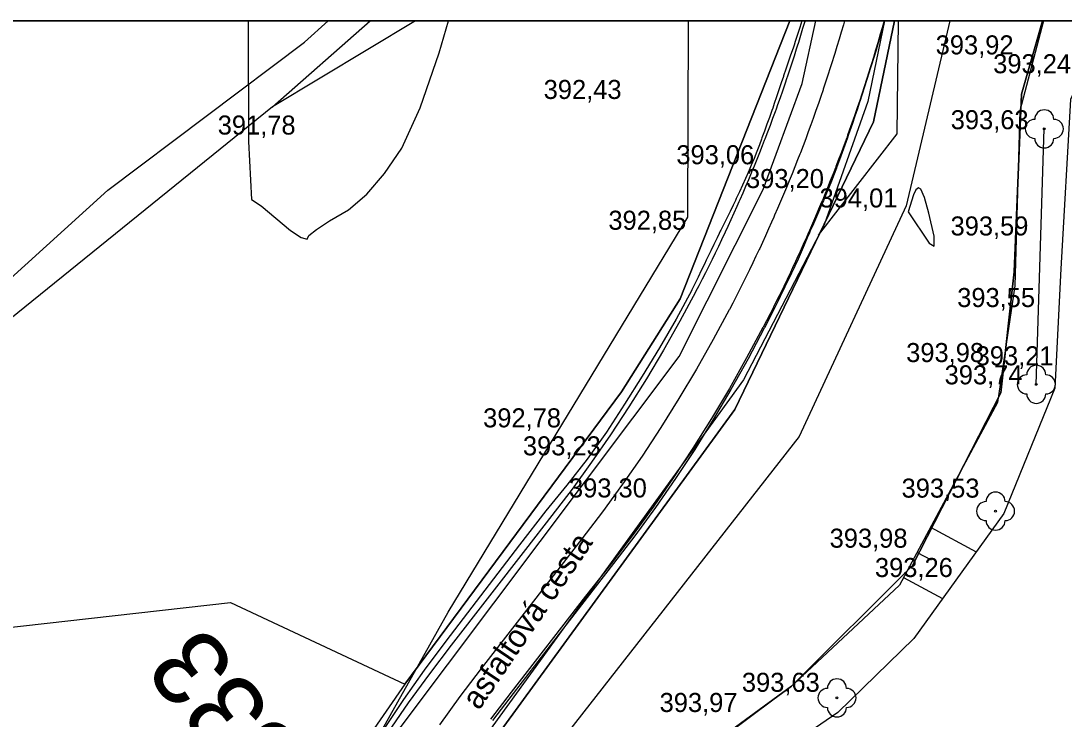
# Model space of a CAD drawing. Extents: x -574342 to -508101, y -1143544 to -1123894.
# Drawn here: x -508550.6 to -508495.8, y -1143152.7 to -1143116.1 of the extents above; entities that cross this region are included whole.
import ezdxf

# ---------------------------------------------------------------- set-up
doc = ezdxf.new("R2010")
doc.units = 0
for name, color, linetype in [('01_PARCELY_NAVRH_PC', 7, 'Continuous'), ('01_PARCELY_NAVRH_VHO', 7, 'Continuous'), ('01_PARCELY_NAVRH_ŽP', 7, 'Continuous'), ('07_VODOVOD', 7, 'Continuous'), ('1000', 7, 'Continuous'), ('15', 7, 'Continuous'), ('18', 7, 'Continuous'), ('21', 7, 'Continuous'), ('37', 7, 'Continuous'), ('42', 7, 'Continuous'), ('51', 7, 'Continuous'), ('54', 7, 'Continuous'), ('55', 7, 'Continuous'), ('60', 7, 'Continuous'), ('61', 7, 'Continuous'), ('Level 1', 7, 'Continuous'), ('Level 255', 7, 'Continuous'), ('tab', 7, 'Continuous'), ('VRST VEDL', 7, 'Continuous')]:
    doc.layers.add(name, color=color, linetype=linetype)

msp = doc.modelspace()

# ---------------------------------------------------------------- linework, layer by layer
at = {"layer": '01_PARCELY_NAVRH_PC'}
msp.add_line((-508504.685, -1143116.058), (-508510.179, -1143116.058), dxfattribs=at)
msp.add_line((-508504.685, -1143116.058), (-508510.179, -1143116.058), dxfattribs=at)
msp.add_lwpolyline([(-508510.179, -1143116.058), (-508515.95, -1143130.65), (-508519.02, -1143135.54), (-508530.41, -1143150.9), (-508533.66, -1143155.6), (-508539.86, -1143167.27), (-508535.17, -1143170.73), (-508529.25, -1143158.67), (-508513.07, -1143136.47), (-508505.79, -1143121.37), (-508504.685, -1143116.058)], dxfattribs=at)
msp.add_lwpolyline([(-508510.179, -1143116.058), (-508515.95, -1143130.65), (-508519.02, -1143135.54), (-508530.41, -1143150.9), (-508533.66, -1143155.6), (-508539.86, -1143167.27), (-508535.17, -1143170.73), (-508529.25, -1143158.67), (-508513.07, -1143136.47), (-508505.79, -1143121.37), (-508504.685, -1143116.058)], dxfattribs=at)
at = {"layer": '01_PARCELY_NAVRH_VHO'}
msp.add_line((-508484.878, -1143116.058), (-508496.906, -1143116.058), dxfattribs=at)
msp.add_lwpolyline([(-508496.906, -1143116.058), (-508498.01, -1143119.91), (-508498.41, -1143129.24), (-508499.11, -1143135.6), (-508503.75, -1143144.67), (-508510.09, -1143151.01), (-508521.99, -1143159.7), (-508523.79, -1143164.91), (-508525.32, -1143175.64), (-508530.07, -1143174.68), (-508516.39, -1143188), (-508504.26, -1143191.1), (-508496.38, -1143198.1)], dxfattribs=at)
at = {"layer": '01_PARCELY_NAVRH_ŽP'}
for p, q in [((-508510.179, -1143116.058), (-508642.792, -1143116.058)), ((-508496.906, -1143116.058), (-508504.685, -1143116.058))]:
    msp.add_line(p, q, dxfattribs=at)
for points in [[(-508642.792, -1143116.058), (-508649.66, -1143119.13), (-508584.79, -1143151.71), (-508539.57, -1143146.61), (-508530.41, -1143150.9), (-508519.02, -1143135.54), (-508515.95, -1143130.65), (-508510.179, -1143116.058)], [(-508504.685, -1143116.058), (-508505.79, -1143121.37), (-508513.07, -1143136.47), (-508529.25, -1143158.67), (-508535.17, -1143170.73), (-508530.07, -1143174.68), (-508525.32, -1143175.64), (-508523.79, -1143164.91), (-508521.99, -1143159.7), (-508510.09, -1143151.01), (-508503.75, -1143144.67), (-508499.11, -1143135.6), (-508498.41, -1143129.24), (-508498.01, -1143119.91), (-508496.906, -1143116.058)], [(-508649.66, -1143119.13), (-508584.79, -1143151.71), (-508539.57, -1143146.61), (-508530.41, -1143150.9), (-508533.66, -1143155.6), (-508539.86, -1143167.27), (-508547.02, -1143163.34), (-508553.27, -1143164.53), (-508559.77, -1143166.35), (-508565.39, -1143163.91), (-508571.39, -1143166.22), (-508578.23, -1143159.53), (-508587.9, -1143163.05), (-508596.45, -1143153.64), (-508600.04, -1143155.89), (-508608.16, -1143150.99), (-508613.1, -1143145.09)]]:
    msp.add_lwpolyline(points, dxfattribs=at)
at = {"layer": '07_VODOVOD'}
msp.add_lwpolyline([(-508640.05, -1143130.18), (-508637.48, -1143128.83), (-508626.48, -1143135.95), (-508617.09, -1143140.73), (-508602.61, -1143146.08), (-508586.87, -1143149.65), (-508578.03, -1143148.66), (-508571.02, -1143145.86), (-508562.51, -1143139.92), (-508546.01, -1143124.95), (-508535.68, -1143117.17), (-508534.428, -1143116.058)], dxfattribs=at)
at = {"layer": '1000'}
for points in [[(-508509.555, -1143116.058), (-508509.662, -1143116.407), (-508509.779, -1143116.772), (-508509.898, -1143117.136), (-508509.963, -1143117.334), (-508510.019, -1143117.5), (-508510.142, -1143117.863), (-508510.266, -1143118.226), (-508510.388, -1143118.59), (-508510.511, -1143118.952), (-508510.523, -1143118.986), (-508510.637, -1143119.314), (-508510.759, -1143119.678), (-508510.88, -1143120.041), (-508511.003, -1143120.404), (-508511.084, -1143120.637), (-508511.129, -1143120.767), (-508511.256, -1143121.128), (-508511.385, -1143121.489), (-508511.516, -1143121.85), (-508511.65, -1143122.209), (-508511.676, -1143122.278), (-508511.785, -1143122.568), (-508511.922, -1143122.926), (-508512.063, -1143123.283), (-508512.213, -1143123.636), (-508512.325, -1143123.897), (-508512.365, -1143123.988), (-508512.519, -1143124.339), (-508512.675, -1143124.689), (-508512.833, -1143125.038), (-508512.996, -1143125.386), (-508513.044, -1143125.487), (-508513.161, -1143125.732), (-508513.328, -1143126.077), (-508513.496, -1143126.421), (-508513.667, -1143126.764), (-508513.812, -1143127.053), (-508513.839, -1143127.107), (-508513.897, -1143127.219), (-508514.007, -1143127.451), (-508514.173, -1143127.796), (-508514.34, -1143128.14), (-508514.509, -1143128.484), (-508514.573, -1143128.621), (-508514.671, -1143128.831), (-508514.835, -1143129.177), (-508515.001, -1143129.523), (-508515.169, -1143129.867), (-508515.328, -1143130.191), (-508515.338, -1143130.211), (-508516.158, -1143131.725), (-508517.034, -1143133.232), (-508517.948, -1143134.715), (-508518.871, -1143136.193), (-508519.819, -1143137.655), (-508520.829, -1143139.074), (-508521.896, -1143140.452), (-508522.999, -1143141.799), (-508524.389, -1143143.582), (-508528.252, -1143148.642), (-508529.383, -1143150.162), (-508530.477, -1143151.708), (-508531.533, -1143153.28)], [(-508509.396, -1143116.058), (-508509.404, -1143116.083), (-508509.512, -1143116.451), (-508509.623, -1143116.819), (-508509.736, -1143117.187), (-508509.797, -1143117.385), (-508509.85, -1143117.553), (-508509.966, -1143117.92), (-508510.084, -1143118.285), (-508510.204, -1143118.65), (-508510.325, -1143119.015), (-508510.336, -1143119.048), (-508510.448, -1143119.379), (-508510.573, -1143119.742), (-508510.7, -1143120.105), (-508510.829, -1143120.467), (-508510.912, -1143120.699), (-508510.959, -1143120.828), (-508511.092, -1143121.189), (-508511.226, -1143121.549), (-508511.361, -1143121.909), (-508511.499, -1143122.267), (-508511.526, -1143122.336), (-508511.638, -1143122.625), (-508511.779, -1143122.983), (-508511.922, -1143123.34), (-508512.067, -1143123.696), (-508512.175, -1143123.959), (-508512.213, -1143124.051), (-508512.361, -1143124.405), (-508512.511, -1143124.759), (-508512.662, -1143125.112), (-508512.816, -1143125.465), (-508512.861, -1143125.568), (-508512.971, -1143125.816), (-508513.127, -1143126.167), (-508513.286, -1143126.517), (-508513.446, -1143126.866), (-508513.583, -1143127.16), (-508513.608, -1143127.215), (-508513.662, -1143127.329), (-508513.772, -1143127.562), (-508513.937, -1143127.909), (-508514.104, -1143128.255), (-508514.273, -1143128.6), (-508514.34, -1143128.736), (-508514.443, -1143128.945), (-508514.616, -1143129.288), (-508514.789, -1143129.631), (-508514.965, -1143129.973), (-508515.132, -1143130.294), (-508515.142, -1143130.313), (-508515.959, -1143131.834), (-508516.82, -1143133.356), (-508517.716, -1143134.857), (-508518.644, -1143136.339), (-508519.606, -1143137.799), (-508520.6, -1143139.237), (-508521.626, -1143140.652), (-508522.683, -1143142.044), (-508524.071, -1143143.829), (-508527.978, -1143148.854), (-508529.119, -1143150.357), (-508530.225, -1143151.886), (-508531.296, -1143153.44)], [(-508505.237, -1143116.058), (-508505.341, -1143116.43), (-508505.451, -1143116.815), (-508505.452, -1143116.819), (-508505.565, -1143117.207), (-508505.679, -1143117.594), (-508505.795, -1143117.981), (-508505.914, -1143118.367), (-508505.979, -1143118.576), (-508506.034, -1143118.753), (-508506.156, -1143119.138), (-508506.28, -1143119.522), (-508506.406, -1143119.906), (-508506.533, -1143120.289), (-508506.545, -1143120.324), (-508506.663, -1143120.672), (-508506.794, -1143121.054), (-508506.928, -1143121.435), (-508507.063, -1143121.816), (-508507.151, -1143122.06), (-508507.2, -1143122.195), (-508507.339, -1143122.575), (-508507.48, -1143122.953), (-508507.623, -1143123.331), (-508507.767, -1143123.708), (-508507.795, -1143123.781), (-508507.914, -1143124.085), (-508508.062, -1143124.461), (-508508.212, -1143124.836), (-508508.364, -1143125.21), (-508508.478, -1143125.487), (-508508.518, -1143125.583), (-508508.674, -1143125.956), (-508508.831, -1143126.328), (-508508.991, -1143126.699), (-508509.152, -1143127.07), (-508509.199, -1143127.178), (-508509.315, -1143127.439), (-508509.48, -1143127.808), (-508509.646, -1143128.176), (-508509.815, -1143128.543), (-508509.958, -1143128.852), (-508509.985, -1143128.909), (-508510.041, -1143129.03), (-508510.157, -1143129.275), (-508510.331, -1143129.639), (-508510.506, -1143130.003), (-508510.684, -1143130.366), (-508510.754, -1143130.508), (-508510.863, -1143130.728), (-508511.044, -1143131.089), (-508511.227, -1143131.449), (-508511.411, -1143131.809), (-508511.587, -1143132.147), (-508511.598, -1143132.167), (-508512.456, -1143133.766), (-508513.362, -1143135.365), (-508514.303, -1143136.944), (-508515.279, -1143138.501), (-508516.29, -1143140.036), (-508517.335, -1143141.548), (-508518.414, -1143143.036), (-508519.526, -1143144.499), (-508520.913, -1143146.284), (-508524.82, -1143151.31), (-508525.906, -1143152.739)], [(-508505.207, -1143116.058), (-508505.315, -1143116.437), (-508505.427, -1143116.822), (-508505.428, -1143116.826), (-508505.542, -1143117.213), (-508505.657, -1143117.6), (-508505.775, -1143117.987), (-508505.894, -1143118.373), (-508505.959, -1143118.582), (-508506.015, -1143118.759), (-508506.137, -1143119.144), (-508506.261, -1143119.528), (-508506.387, -1143119.912), (-508506.514, -1143120.296), (-508506.525, -1143120.331), (-508506.64, -1143120.679), (-508506.768, -1143121.063), (-508506.898, -1143121.445), (-508507.03, -1143121.828), (-508507.115, -1143122.073), (-508507.163, -1143122.209), (-508507.297, -1143122.59), (-508507.434, -1143122.971), (-508507.572, -1143123.351), (-508507.712, -1143123.73), (-508507.739, -1143123.803), (-508507.853, -1143124.108), (-508508.002, -1143124.484), (-508508.155, -1143124.859), (-508508.31, -1143125.232), (-508508.426, -1143125.509), (-508508.467, -1143125.604), (-508508.625, -1143125.976), (-508508.786, -1143126.347), (-508508.947, -1143126.718), (-508509.111, -1143127.087), (-508509.159, -1143127.195), (-508509.271, -1143127.459), (-508509.426, -1143127.832), (-508509.583, -1143128.205), (-508509.752, -1143128.572), (-508509.895, -1143128.881), (-508509.922, -1143128.939), (-508509.979, -1143129.059), (-508510.094, -1143129.304), (-508510.268, -1143129.67), (-508510.443, -1143130.034), (-508510.62, -1143130.397), (-508510.69, -1143130.54), (-508510.798, -1143130.76), (-508510.978, -1143131.122), (-508511.16, -1143131.484), (-508511.343, -1143131.844), (-508511.517, -1143132.183), (-508511.528, -1143132.204), (-508512.378, -1143133.809), (-508513.282, -1143135.412), (-508514.214, -1143136.998), (-508515.181, -1143138.564), (-508516.196, -1143140.1), (-508517.247, -1143141.61), (-508518.326, -1143143.101), (-508519.439, -1143144.567), (-508520.824, -1143146.354), (-508524.724, -1143151.384), (-508525.806, -1143152.813)]]:
    msp.add_lwpolyline(points, dxfattribs=at)
at = {"layer": '21'}
msp.add_lwpolyline([(-508507.315, -1143116.058), (-508507.373, -1143116.263), (-508507.374, -1143116.266), (-508507.484, -1143116.645), (-508507.596, -1143117.023), (-508507.709, -1143117.4), (-508507.825, -1143117.777), (-508507.888, -1143117.981), (-508507.942, -1143118.153), (-508508.061, -1143118.529), (-508508.182, -1143118.904), (-508508.305, -1143119.278), (-508508.429, -1143119.652), (-508508.441, -1143119.686), (-508508.556, -1143120.025), (-508508.684, -1143120.398), (-508508.814, -1143120.77), (-508508.946, -1143121.141), (-508509.032, -1143121.379), (-508509.08, -1143121.512), (-508509.215, -1143121.882), (-508509.353, -1143122.251), (-508509.492, -1143122.62), (-508509.633, -1143122.988), (-508509.66, -1143123.059), (-508509.776, -1143123.355), (-508509.921, -1143123.722), (-508510.067, -1143124.088), (-508510.215, -1143124.453), (-508510.327, -1143124.723), (-508510.366, -1143124.817), (-508510.517, -1143125.181), (-508510.671, -1143125.544), (-508510.827, -1143125.906), (-508510.984, -1143126.267), (-508511.03, -1143126.373), (-508511.143, -1143126.628), (-508511.304, -1143126.987), (-508511.466, -1143127.346), (-508511.63, -1143127.705), (-508511.77, -1143128.006), (-508511.796, -1143128.062), (-508511.852, -1143128.18), (-508511.964, -1143128.419), (-508512.134, -1143128.774), (-508512.305, -1143129.129), (-508512.478, -1143129.483), (-508512.547, -1143129.622), (-508512.653, -1143129.836), (-508512.83, -1143130.189), (-508513.008, -1143130.54), (-508513.188, -1143130.891), (-508513.359, -1143131.22), (-508513.37, -1143131.24), (-508514.208, -1143132.8), (-508515.091, -1143134.36), (-508516.009, -1143135.901), (-508516.962, -1143137.42), (-508517.948, -1143138.917), (-508518.968, -1143140.392), (-508520.02, -1143141.844), (-508521.105, -1143143.272), (-508522.492, -1143145.057), (-508526.399, -1143150.082), (-508527.512, -1143151.548), (-508528.592, -1143153.04)], dxfattribs=at)
at = {"layer": '37'}
for points in [[(-508511.59, -1143124.92), (-508509.54, -1143119.35), (-508508.823, -1143116.058)], [(-508511.59, -1143124.92), (-508509.54, -1143119.35), (-508508.823, -1143116.058)], [(-508505.208, -1143116.058), (-508506.09, -1143120.3), (-508508.39, -1143126.78)], [(-508505.208, -1143116.058), (-508506.09, -1143120.3), (-508508.39, -1143126.78)], [(-508544.44, -1143182.59), (-508541.04, -1143171.49), (-508533.03, -1143156.36), (-508515.99, -1143133.69), (-508511.59, -1143124.92)], [(-508544.44, -1143182.59), (-508541.04, -1143171.49), (-508533.03, -1143156.36), (-508515.99, -1143133.69), (-508511.59, -1143124.92)], [(-508508.39, -1143126.78), (-508512.62, -1143134.91), (-508529.52, -1143158.24), (-508537.33, -1143172.61), (-508540.68, -1143183.59)], [(-508508.39, -1143126.78), (-508512.62, -1143134.91), (-508529.52, -1143158.24), (-508537.33, -1143172.61), (-508540.68, -1143183.59)]]:
    msp.add_lwpolyline(points, dxfattribs=at)
at = {"layer": '42'}
for points in [[(-508584.52, -1143185.46), (-508576.94, -1143184.13), (-508565.72, -1143180.04), (-508541.6, -1143171.1), (-508528.13, -1143147.12), (-508515.55, -1143126.37), (-508515.51, -1143116.058)], [(-508584.52, -1143185.46), (-508576.94, -1143184.13), (-508565.72, -1143180.04), (-508541.6, -1143171.1), (-508528.13, -1143147.12), (-508515.55, -1143126.37), (-508515.51, -1143116.058)], [(-508537.36, -1143120.57), (-508532.229, -1143116.058)], [(-508537.36, -1143120.57), (-508532.229, -1143116.058)], [(-508529.847, -1143116.058), (-508537.36, -1143120.57)], [(-508529.847, -1143116.058), (-508537.36, -1143120.57)], [(-508529.847, -1143116.058), (-508537.36, -1143120.57)], [(-508529.847, -1143116.058), (-508537.36, -1143120.57)], [(-508537.36, -1143120.57), (-508572.46, -1143148.95), (-508584.79, -1143151.71), (-508598.2, -1143149.51), (-508615.67, -1143142.95), (-508625.58, -1143137.77), (-508636.15, -1143129.8), (-508644.59, -1143122.18), (-508650.46, -1143119.78), (-508658.6, -1143119.8), (-508680.31, -1143123.88), (-508697.98, -1143132.18), (-508703.096, -1143133.592)], [(-508537.36, -1143120.57), (-508572.46, -1143148.95), (-508584.79, -1143151.71), (-508598.2, -1143149.51), (-508615.67, -1143142.95), (-508625.58, -1143137.77), (-508636.15, -1143129.8), (-508644.59, -1143122.18), (-508650.46, -1143119.78), (-508658.6, -1143119.8), (-508680.31, -1143123.88), (-508697.98, -1143132.18), (-508703.096, -1143133.592)]]:
    msp.add_lwpolyline(points, dxfattribs=at)
at = {"layer": '51'}
msp.add_lwpolyline([(-508493.571, -1143116.058), (-508495.44, -1143120.19), (-508495.95, -1143129.08), (-508496.26, -1143135.35), (-508498.94, -1143141.93), (-508503.68, -1143148.5), (-508507.66, -1143152.38), (-508520.2, -1143160.98), (-508521.82, -1143163.95), (-508518.57, -1143168.12), (-508515.5, -1143169.45), (-508512.14, -1143168.95), (-508504.12, -1143160.81), (-508497.6, -1143155.8), (-508487.25, -1143151.23), (-508483.67, -1143147.96), (-508481.24, -1143143.89), (-508482.47, -1143135.96), (-508484.03, -1143128.35), (-508484.73, -1143123.98), (-508486.94, -1143118.54), (-508489.496, -1143116.058)], dxfattribs=at)
msp.add_lwpolyline([(-508493.571, -1143116.058), (-508495.44, -1143120.19), (-508495.95, -1143129.08), (-508496.26, -1143135.35), (-508498.94, -1143141.93), (-508503.68, -1143148.5), (-508507.66, -1143152.38), (-508520.2, -1143160.98), (-508521.82, -1143163.95), (-508518.57, -1143168.12), (-508515.5, -1143169.45), (-508512.14, -1143168.95), (-508504.12, -1143160.81), (-508497.6, -1143155.8), (-508487.25, -1143151.23), (-508483.67, -1143147.96), (-508481.24, -1143143.89), (-508482.47, -1143135.96), (-508484.03, -1143128.35), (-508484.73, -1143123.98), (-508486.94, -1143118.54), (-508489.496, -1143116.058)], dxfattribs=at)
at = {"layer": '54'}
for centre in [(-508496.82, -1143121.73), (-508497.24, -1143135.15), (-508499.38, -1143141.81), (-508507.71, -1143151.62)]:
    msp.add_circle(centre, 0.05, dxfattribs=at)
for centre, start, end in [((-508496.82, -1143121.23), 0, 180), ((-508497.32, -1143121.73), 90, 270), ((-508496.32, -1143121.73), 270, 90), ((-508496.82, -1143122.23), 180, 0), ((-508497.24, -1143134.65), 0, 180), ((-508497.74, -1143135.15), 90, 270), ((-508496.74, -1143135.15), 270, 90), ((-508497.24, -1143135.65), 180, 0), ((-508499.38, -1143141.31), 0, 180), ((-508499.88, -1143141.81), 90, 270), ((-508498.88, -1143141.81), 270, 90), ((-508499.38, -1143142.31), 180, 0), ((-508507.71, -1143151.12), 0, 180), ((-508508.21, -1143151.62), 90, 270), ((-508507.21, -1143151.62), 270, 90), ((-508507.71, -1143152.12), 180, 0)]:
    msp.add_arc(centre, 0.5, start, end, dxfattribs=at)
at = {"layer": '55'}
msp.add_line((-508497.24, -1143135.15), (-508496.82, -1143121.73), dxfattribs=at)
msp.add_line((-508497.24, -1143135.15), (-508496.82, -1143121.73), dxfattribs=at)
msp.add_lwpolyline([(-508501.781, -1143116.058), (-508504.08, -1143125.77), (-508509.69, -1143137.89), (-508528.17, -1143161.51)], dxfattribs=at)
msp.add_lwpolyline([(-508501.781, -1143116.058), (-508504.08, -1143125.77), (-508509.69, -1143137.89), (-508528.17, -1143161.51)], dxfattribs=at)
at = {"layer": '60'}
msp.add_lwpolyline([(-508496.861, -1143116.058), (-508498.11, -1143120.78), (-508498.36, -1143129.97), (-508499.28, -1143136.1), (-508504.42, -1143145.69), (-508510.09, -1143151.01), (-508522.36, -1143160.17), (-508523.76, -1143165.4), (-508522.03, -1143168.68), (-508525.16, -1143176.55)], dxfattribs=at)
msp.add_lwpolyline([(-508496.861, -1143116.058), (-508498.11, -1143120.78), (-508498.36, -1143129.97), (-508499.28, -1143136.1), (-508504.42, -1143145.69), (-508510.09, -1143151.01), (-508522.36, -1143160.17), (-508523.76, -1143165.4), (-508522.03, -1143168.68), (-508525.16, -1143176.55)], dxfattribs=at)
msp.add_lwpolyline([(-508496.861, -1143116.058), (-508498.11, -1143120.78), (-508498.36, -1143129.97), (-508499.28, -1143136.1), (-508504.42, -1143145.69), (-508510.09, -1143151.01), (-508522.36, -1143160.17), (-508523.76, -1143165.4), (-508522.03, -1143168.68), (-508525.16, -1143176.55)], dxfattribs=at)
msp.add_lwpolyline([(-508496.861, -1143116.058), (-508498.11, -1143120.78), (-508498.36, -1143129.97), (-508499.28, -1143136.1), (-508504.42, -1143145.69), (-508510.09, -1143151.01), (-508522.36, -1143160.17), (-508523.76, -1143165.4), (-508522.03, -1143168.68), (-508525.16, -1143176.55)], dxfattribs=at)
at = {"layer": '61'}
for p, q in [((-508502.794, -1143142.656), (-508500.393, -1143143.943)), ((-508502.794, -1143142.656), (-508500.393, -1143143.943)), ((-508503.503, -1143143.978), (-508502.762, -1143144.375)), ((-508503.503, -1143143.978), (-508502.762, -1143144.375)), ((-508504.211, -1143145.3), (-508502.163, -1143146.398)), ((-508504.211, -1143145.3), (-508502.163, -1143146.398))]:
    msp.add_line(p, q, dxfattribs=at)
at = {"layer": 'Level 1'}
msp.add_lwpolyline([(-508703.096, -1143116.058), (-508109.096, -1143116.058), (-508109.096, -1143536.058), (-508703.096, -1143536.058)], close=True, dxfattribs=at)
at = {"layer": 'tab'}
msp.add_lwpolyline([(-508504.495, -1143116.058), (-508504.559, -1143121.991), (-508508.695, -1143127.311)], dxfattribs=at)
at = {"layer": 'VRST VEDL'}
msp.add_line((-508528.113, -1143116.058), (-508538.628, -1143116.058), dxfattribs=at)
msp.add_lwpolyline([(-508538.628, -1143116.058), (-508538.632, -1143116.449), (-508538.61, -1143122.393), (-508538.469, -1143125.446), (-508537.951, -1143125.773), (-508536.405, -1143127.07), (-508535.858, -1143127.439), (-508535.539, -1143127.527), (-508535.446, -1143127.336), (-508535.054, -1143127.016), (-508534.363, -1143126.567), (-508533.373, -1143125.99), (-508532.41, -1143125.16), (-508531.474, -1143124.075), (-508530.565, -1143122.736), (-508529.606, -1143120.624), (-508528.599, -1143117.74), (-508528.113, -1143116.058)], dxfattribs=at)
msp.add_lwpolyline([(-508503.962, -1143126.086), (-508502.87, -1143127.74), (-508502.599, -1143127.891), (-508502.603, -1143127.367), (-508502.883, -1143126.167), (-508503.114, -1143125.343), (-508503.297, -1143124.896), (-508503.433, -1143124.825), (-508503.567, -1143124.926), (-508503.699, -1143125.198)], close=True, dxfattribs=at)

# ---------------------------------------------------------------- texts
at = {"layer": '15'}
msp.add_text('asfaltová cesta', height=1.2, rotation=55.8061, dxfattribs=at).set_placement((-508526.513, -1143152.312))
msp.add_text('asfaltová cesta', height=1.2, rotation=55.8061, dxfattribs=at).set_placement((-508526.513, -1143152.312))
at = {"layer": '18'}
msp.add_text('0+333', height=4, rotation=128.6295, dxfattribs=at).set_placement((-508531.646, -1143159.406))
at = {"layer": 'Level 255'}
for s, p in [('393,92', (-508502.525, -1143117.82)), ('393,24', (-508499.505, -1143118.81)), ('392,43', (-508523.115, -1143120.16)), ('393,63', (-508501.735, -1143121.75)), ('391,78', (-508540.235, -1143122.03)), ('393,06', (-508516.145, -1143123.59)), ('393,20', (-508512.485, -1143124.84)), ('394,01', (-508508.625, -1143125.86)), ('392,85', (-508519.715, -1143127.03)), ('393,59', (-508501.745, -1143127.33)), ('393,55', (-508501.395, -1143131.09)), ('393,98', (-508504.075, -1143133.98)), ('393,21', (-508500.425, -1143134.15)), ('393,74', (-508502.055, -1143135.15)), ('392,78', (-508526.295, -1143137.41)), ('393,23', (-508524.205, -1143138.88)), ('393,30', (-508521.785, -1143141.09)), ('393,53', (-508504.315, -1143141.1)), ('393,98', (-508508.095, -1143143.73)), ('393,26', (-508505.715, -1143145.27)), ('393,63', (-508512.705, -1143151.3)), ('393,97', (-508517.025, -1143152.36))]:
    msp.add_text(s, height=1, dxfattribs=at).set_placement(p)

doc.saveas('drawing.dxf')
